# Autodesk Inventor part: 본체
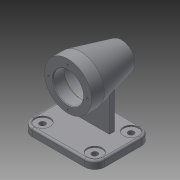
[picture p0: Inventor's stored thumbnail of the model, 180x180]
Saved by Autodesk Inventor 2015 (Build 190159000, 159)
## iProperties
Created: 2024-12
Part Number: 본체
Material: 일반
Document SubType Name: Modeling
Designer: 10402
Density: 1 g/cm^3
Appearance: 기본값
Author: 10402
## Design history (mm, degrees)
sketch "스케치1"
  geometry: L1 (-57, 44.5)-(57, 44.5); L2 (57, 44.5)-(57, -44.5); L3 (57, -44.5)-(-57, -44.5); L4 (-57, -44.5)-(-57, 44.5); L5 (-57, 44.5)-(57, -44.5); L6 (57, 44.5)-(-57, -44.5); 1 further point
  constraints: 12 end point, 2 midpoint, 2 parallel, 1 horizontal, 1 perpendicular
  dimensions: "d0" = 114 distance of L2.end L3.end; "d1" = 89 distance of L1.end L2.end
extrude "돌출1" new body sketch "스케치1" distance "d2" = 12; taper "d3" = 0 deg
fillet "모깎기1" dims "d4" = 16
sketch "스케치2"
  geometry: A1 r 16 centre (-41, 28.5) between (-41, 44.5) and (-57, 28.5) reference; A2 r 16 centre (-41, -28.5) between (-57, -28.5) and (-41, -44.5) reference; A3 r 16 centre (41, -28.5) between (41, -44.5) and (57, -28.5) reference; A4 r 16 centre (41, 28.5) between (57, 28.5) and (41, 44.5) reference; 1 further point
hole "구멍1" sketch "스케치2" at (-41, 28.5), (41, 28.5), (41, -28.5), (-41, -28.5) diameter "d5" = 9; stored, may be unused: countersink angle "d9" = 90 deg, drill point angle "d11" = 118 deg; dims "d6" = 6, "d7" = 24, "d8" = 2, "d10" = 8
fillet "모깎기2" dims "d12" = 3
sketch "스케치4"
  geometry: L1 (44.5, 9)-(44.5, 0) reference; L2 (44.5, 0)-(-44.5, 0) reference; L3 (-44.5, 0)-(-44.5, 9) reference; L4 (-41.5, 12)-(41.5, 12) reference; L5 (-29.5, 119)-(-9.5, 119); L6 (54.5, 103)-(54.5, 82); L7 (54.5, 82)-(-29.5, 82); L8 (-29.5, 82)-(-29.5, 119); L9 (54.5, 103)-(-9.5, 119); A1 r 3 centre (41.5, 9) between (44.5, 9) and (41.5, 12) reference; A2 r 3 centre (-41.5, 9) between (-41.5, 12) and (-44.5, 9) reference; 1 further point
  constraints: 10 end point, 2 parallel, 1 horizontal, 1 perpendicular
  dimensions: "d20" = 84 distance between parallel lines of L6 L8; "d21" = 15 distance between parallel lines of L8 L3; "d22" = 20 distance of L5.end L5.start; "d23" = 37 distance between parallel lines of L7 L5; "d24" = 21 distance of L6.start L6.end; "d25" = 82 distance between parallel lines of L2 L7
revolve "회전2" sketch "스케치4" stored, may be unused: angle "d26" = 90 deg
sketch "스케치5"
  geometry: L1 (28, 15.5)-(-28, 15.5); L2 (-28, 15.5)-(-28, 7.5); L3 (-28, 7.5)-(28, 7.5); L4 (28, 7.5)-(28, 15.5); L5 (41, 44.5)-(-41, 44.5) reference; L6 (-5, 44.5)-(5, 44.5); L7 (5, 44.5)-(5, -37.5); L8 (5, -37.5)-(-5, -37.5); L9 (-5, -37.5)-(-5, 44.5); L10 (-41, -44.5)-(41, -44.5) reference; 3 further points
  constraints: 16 end point, 4 parallel, 2 horizontal, 2 midpoint, 2 perpendicular, 2 vertical alignment, 1 point on line
  dimensions: "d27" = 8 distance between parallel lines of L3 L1; "d28" = 56 distance between parallel lines of L4 L2; "d29" = 29 distance between parallel lines of L1 L5; "d30" = 10 distance between parallel lines of L7 L9; "d31" = 7 distance between parallel lines of L10 L8
extrude "돌출2" join sketch "스케치5" stored distance "d32" = 12; taper "d33" = 0 deg
sketch "스케치6"
  geometry: L1 (44.5, 9)-(44.5, 0) reference; L2 (44.5, 0)-(-44.5, 0) reference; L3 (-44.5, 0)-(-44.5, 9) reference; L4 (-41.5, 12)-(7.5, 12) reference; L5 (7.5, 12)-(7.5, 49.25) reference; L6 (7.5, 49.25)-(-9.5, 45) reference; L7 (-9.5, 45)-(-29.5, 45) reference; L8 (-29.5, 45)-(-29.5, 119) reference; L9 (-29.5, 119)-(-9.5, 119) reference; L10 (-9.5, 119)-(54.5, 103) reference; L11 (54.5, 103)-(54.5, 61) reference; L12 (54.5, 61)-(15.5, 51.25) reference; L13 (15.5, 51.25)-(15.5, 12) reference; L14 (15.5, 12)-(41.5, 12) reference; L15 (-11.5, 109.3)-(-11.5, 82); L16 (33.5, 102.01)-(33.5, 82); L17 (-11.5, 82)-(33.5, 82); L18 (-5.275, 114.147)-(31.235, 104.919); A1 r 3 centre (41.5, 9) between (44.5, 9) and (41.5, 12) reference; A2 r 3 centre (-41.5, 9) between (-41.5, 12) and (-44.5, 9) reference; A3 r 5 centre (-6.5, 109.3) between (-5.275, 114.147) and (-11.5, 109.3); A4 r 3 centre (30.5, 102.01) between (33.5, 102.01) and (31.235, 104.919); 1 further point
  constraints: 8 end point, 4 point on circle, 4 tangent, 2 centre point, 2 vertical, 1 horizontal
  dimensions: "d35" = 18 distance between parallel lines of L8 L15; "d36" = 45 distance between parallel lines of L15 L16; "d37" = 5 radius of A3; "d38" = 3 radius of A4
revolve "회전3" sketch "스케치6" stored, may be unused: angle "d39" = 90 deg
sketch "스케치7"
  geometry: C1 r 23.5 at (0, -1.898); 1 further point
  constraints: 1 centre point
  dimensions: "d40" = 47 diameter of C1
extrude "돌출3" cut sketch "스케치7" distance "d41" = 18; taper "d42" = 0 deg
sketch "스케치8"
  geometry: C1 r 20.01 at (0, 0) reference; C2 r 17.5 at (0, 0); 1 further point
  constraints: 1 centre point, 1 coincident
  dimensions: "d43" = 35 diameter of C2
extrude "돌출4" cut sketch "스케치8" distance "d44" = 10; taper "d45" = 0 deg
sketch "스케치9"
  geometry: C1 r 17.5 at (0, 0) reference; C2 r 15.5 at (0, 0); 1 further point
  constraints: 1 centre point, 1 coincident
  dimensions: "d46" = 31 diameter of C2
extrude "돌출5" cut sketch "스케치9" distance "d47" = 3; taper "d48" = 0 deg
fillet "모깎기3" dims "d49" = 0.3
chamfer "모따기1" distance "d50" = 1; stored, may be unused: second distance "d51" = 2, angle "d52" = 45 deg
fillet "모깎기4" dims "d53" = 3
sketch "스케치10"
  geometry: C1 r 37 at (0, 0) reference; 2 further points
  constraints: 1 vertical alignment
  dimensions: "d54" = 28.5 distance of C1.centre point (0, 28.5)
hole "구멍2" sketch "스케치10" at (0, 28.5) diameter "d55" = 3.242; stored, may be unused: countersink angle "d59" = 90 deg, drill point angle "d61" = 118 deg; dims "d56" = 8, "d57" = 24, "d58" = 2, "d60" = 10
node "솔리드1"
pattern_circular "원형 패턴1" dims angle "d63" = 360 deg
node "절단 모서리 투영2"
node "절단 모서리 투영3"
